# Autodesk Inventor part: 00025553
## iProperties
Created: 2011-06
Part Number: 00025553
Document SubType Name: Modeling
Designer: Administrator
Density: 2.71 g/cm^3
Material: Aluminum-6061
Mass: 43.8778 g
Surface Area: 82.0261 cm^2
Volume: 16.1911 cm^3
Author: Administrator
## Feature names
1. Base1
